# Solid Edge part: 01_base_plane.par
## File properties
Author: edge
Template: Normal.par
Last saved by: edge
Revision: 14
Application: Solid Edge
非切断部品: False
文書内容のタイプ: 0
Accuracy: 0.99
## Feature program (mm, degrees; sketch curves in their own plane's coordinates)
sketch for "unnamed Protrusion 1" plane through (0, 0, 0) normal (1, 0, 0) x-axis (0, 1, 0)
  line (-24.4872, 29.567) -> (27.8738, 29.567)
  line (27.8738, 29.567) -> (64.0836, -30.088)
  line (33.1385, -53.0757) -> (64.0836, -30.088)
  line (-59.6924, -30.84) -> (33.1385, -53.0757)
  line (-59.6924, -30.84) -> (-24.4872, 29.567)
extrude "unnamed Protrusion 1" add finite 30 symmetric
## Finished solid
Body 1: solid body, 7 faces, 15 edges, 10 vertices.
  Faces by surface: plane 7
  Edges by curve: line 15
Bounding box of the edges (mm): 30.000 x 123.776 x 82.643, from (-15, -59.6924, -53.0757) to (15, 64.0836, 29.567).
Planar faces by outward normal: +x 1, +z 1, -x 1, oblique 4
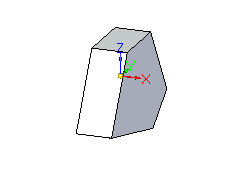
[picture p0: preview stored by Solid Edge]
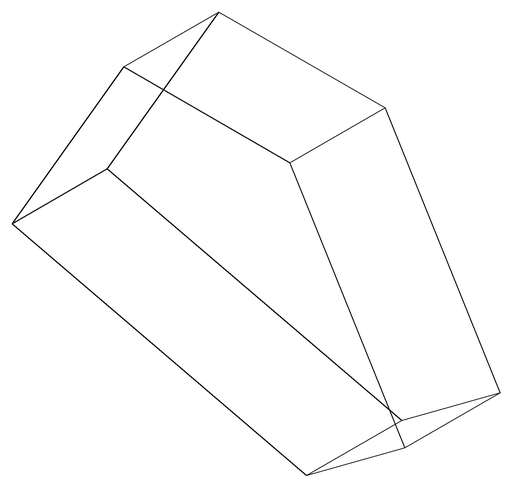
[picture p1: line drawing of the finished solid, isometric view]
